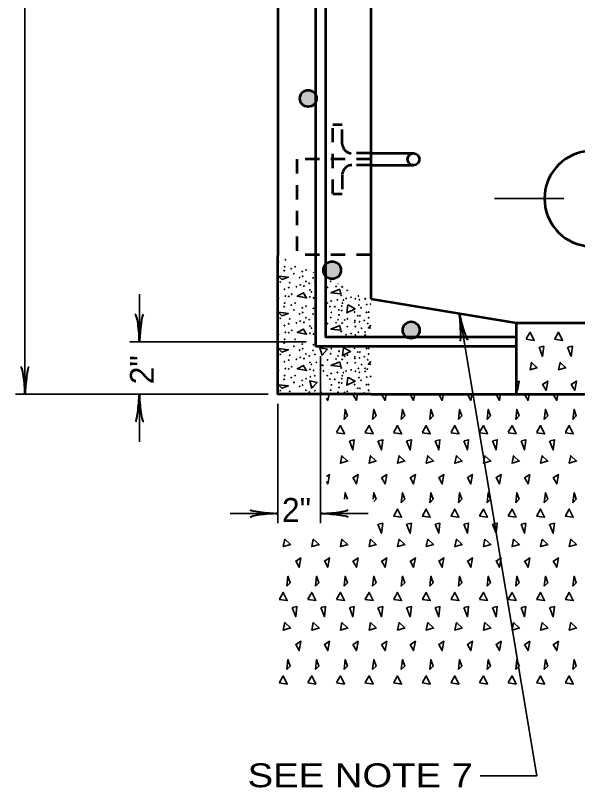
# Model space of a CAD drawing. Extents: x 788 to 1469, y -1 to 439.
# Drawn here: x 856.9 to 915.8, y 80.5 to 161.4 of the extents above; entities that cross this region are included whole.
import ezdxf

# ---------------------------------------------------------------- set-up
doc = ezdxf.new("R2010")
doc.units = 0
doc.linetypes.add('SHORT_DASHED', pattern=[2.7, 1.5, -1.2])
doc.layers.add('1', color=7, linetype='Continuous', lineweight=35)

msp = doc.modelspace()

# ---------------------------------------------------------------- hatches: boundary and pattern name
at = {"layer": '1'}
for points in [[(888.429, 152.704, 1), (886.678, 152.704, 1)], [(890.992, 134.704, 1), (889.144, 134.704, 1)], [(899.239, 128.43, 1), (897.469, 128.43, 1)]]:
    msp.add_hatch(color=256, dxfattribs=at).paths.add_polyline_path(points)

# ---------------------------------------------------------------- linework, layer by layer
for p, q in [((857.856, 195.872), (857.856, 121.703)), ((907.106, 142.203), (914.356, 142.203)), ((869.856, 127.203), (869.856, 132.203)), ((887.356, 127.203), (868.856, 127.203)), ((888.856, 125.703), (888.856, 108.203)), ((883.356, 121.703), (856.856, 121.703)), ((869.856, 121.703), (869.856, 116.703)), ((892.333, 121.738), (892.231, 121.673)), ((895.333, 121.738), (895.231, 121.673)), ((898.333, 121.738), (898.231, 121.673)), ((901.333, 121.738), (901.231, 121.673)), ((904.333, 121.738), (904.231, 121.673)), ((907.333, 121.738), (907.231, 121.673)), ((910.333, 121.738), (910.231, 121.673)), ((913.333, 121.738), (913.231, 121.673)), ((884.356, 120.703), (884.356, 108.203)), ((884.356, 109.203), (879.356, 109.203)), ((888.856, 109.203), (893.856, 109.203))]:
    msp.add_line(p, q, dxfattribs=at)
at = {"layer": '1', "lineweight": 53}
for p, q in [((884.356, 165.102), (884.356, 136.23)), ((894.126, 165.102), (894.126, 131.703)), ((894.126, 146.953), (898.626, 146.953)), ((894.126, 145.703), (898.626, 145.703)), ((894.126, 131.703), (909.356, 129.203)), ((909.356, 129.203), (925.356, 129.203)), ((909.356, 129.203), (909.356, 121.703)), ((894.126, 121.703), (939.409, 121.703))]:
    msp.add_line(p, q, dxfattribs=at)
at = {"layer": '1', "linetype": 'SHORT_DASHED', "lineweight": 53}
for p, q in [((891.126, 147.953), (891.126, 149.953)), ((894.126, 146.953), (892.126, 146.953)), ((894.126, 146.328), (886.366, 146.328)), ((886.366, 146.328), (886.366, 136.328)), ((894.126, 145.703), (892.126, 145.703)), ((891.126, 144.703), (891.126, 142.703)), ((890.126, 142.703), (891.126, 142.703)), ((894.126, 136.328), (886.366, 136.328))]:
    msp.add_line(p, q, dxfattribs=at)
at = {"layer": '1', "lineweight": 53}
msp.add_lwpolyline([(888.356, 126.703), (888.356, 187.287), (889.356, 187.287), (889.356, 127.703), (909.356, 127.703), (909.356, 126.703)], close=True, dxfattribs=at)
at = {"layer": '1', "linetype": 'SHORT_DASHED', "lineweight": 53}
msp.add_lwpolyline([(890.126, 142.703), (890.126, 149.953), (891.126, 149.953)], dxfattribs=at)
at = {"layer": '1', "lineweight": 53}
msp.add_lwpolyline([(894.126, 121.703), (884.356, 121.703), (884.356, 136.23)], dxfattribs=at)
at = {"layer": '1'}
for points in [[(884.356, 136.21), (884.363, 136.21), (884.356, 136.223)], [(890.883, 132.71), (889.943, 132.33), (890.983, 132.21), (890.883, 132.67)], [(884.356, 132.41), (884.363, 132.41), (884.356, 132.423)], [(887.063, 132.33), (886.403, 131.97), (887.383, 131.79), (887.023, 132.35)], [(891.763, 131.07), (892.463, 130.67), (891.603, 130.25), (891.723, 131.09)], [(903.41, 130.179), (911.52, 81.73), (905.579, 81.73)], [(890.883, 128.91), (889.943, 128.53), (890.983, 128.41), (890.883, 128.87)], [(894.126, 128.927), (893.863, 128.65), (894.126, 128.632)], [(884.356, 128.61), (884.363, 128.61), (884.356, 128.623)], [(887.063, 128.53), (886.403, 128.17), (887.383, 127.99), (887.023, 128.55)], [(910.417, 127.505), (910.817, 128.205), (911.237, 127.345), (910.397, 127.465)], [(913.417, 127.505), (913.817, 128.205), (914.237, 127.345), (913.397, 127.465)], [(889.023, 125.774), (888.783, 126.574), (889.563, 126.414), (889.003, 125.814)], [(891.3, 126.567), (892, 126.167), (891.14, 125.747), (891.26, 126.587)], [(911.757, 126.625), (912.137, 125.665), (912.257, 126.725), (911.797, 126.625)], [(914.757, 126.625), (915.137, 125.665), (915.257, 126.725), (914.797, 126.625)], [(884.356, 124.81), (884.363, 124.81), (884.356, 124.823)], [(887.063, 124.73), (886.403, 124.37), (887.383, 124.19), (887.023, 124.75)], [(890.883, 125.11), (889.943, 124.73), (890.983, 124.61), (890.883, 125.07)], [(894.126, 125.127), (893.863, 124.85), (894.126, 124.832)], [(911.617, 124.505), (910.817, 124.265), (910.977, 125.045), (911.577, 124.485)], [(914.617, 124.505), (913.817, 124.265), (913.977, 125.045), (914.577, 124.485)], [(887.95, 122.307), (887.711, 123.107), (888.49, 122.947), (887.93, 122.347)], [(891.763, 123.47), (892.463, 123.07), (891.603, 122.65), (891.723, 123.49)], [(909.356, 122.363), (909.497, 122.105), (909.677, 123.085), (909.356, 122.879)], [(912.137, 122.765), (912.497, 122.105), (912.677, 123.085), (912.117, 122.725)], [(915.137, 122.765), (915.497, 122.105), (915.677, 123.085), (915.117, 122.725)], [(889.485, 121.285), (889.611, 121.053), (889.737, 121.738)], [(892.251, 121.713), (892.611, 121.053), (892.737, 121.738)], [(895.251, 121.713), (895.611, 121.053), (895.737, 121.738)], [(898.251, 121.713), (898.611, 121.053), (898.737, 121.738)], [(901.251, 121.713), (901.611, 121.053), (901.737, 121.738)], [(904.251, 121.713), (904.611, 121.053), (904.737, 121.738)], [(907.251, 121.713), (907.611, 121.053), (907.737, 121.738)], [(910.251, 121.713), (910.611, 121.053), (910.737, 121.738)], [(913.251, 121.713), (913.611, 121.053), (913.737, 121.738)], [(890.531, 117.713), (890.931, 118.413), (891.351, 117.553), (890.511, 117.673)], [(893.531, 117.713), (893.931, 118.413), (894.351, 117.553), (893.511, 117.673)], [(896.531, 117.713), (896.931, 118.413), (897.351, 117.553), (896.511, 117.673)], [(899.531, 117.713), (899.931, 118.413), (900.351, 117.553), (899.511, 117.673)], [(902.531, 117.713), (902.931, 118.413), (903.351, 117.553), (902.511, 117.673)], [(905.531, 117.713), (905.931, 118.413), (906.351, 117.553), (905.511, 117.673)], [(908.531, 117.713), (908.931, 118.413), (909.351, 117.553), (908.511, 117.673)], [(911.531, 117.713), (911.931, 118.413), (912.351, 117.553), (911.511, 117.673)], [(914.531, 117.713), (914.931, 118.413), (915.351, 117.553), (914.511, 117.673)], [(891.871, 116.833), (892.251, 115.873), (892.371, 116.933), (891.911, 116.833)], [(894.871, 116.833), (895.251, 115.873), (895.371, 116.933), (894.911, 116.833)], [(897.871, 116.833), (898.251, 115.873), (898.371, 116.933), (897.911, 116.833)], [(900.871, 116.833), (901.251, 115.873), (901.371, 116.933), (900.911, 116.833)], [(903.871, 116.833), (904.251, 115.873), (904.371, 116.933), (903.911, 116.833)], [(906.871, 116.833), (907.251, 115.873), (907.371, 116.933), (906.911, 116.833)], [(909.871, 116.833), (910.251, 115.873), (910.371, 116.933), (909.911, 116.833)], [(912.871, 116.833), (913.251, 115.873), (913.371, 116.933), (912.911, 116.833)], [(891.731, 114.713), (890.931, 114.473), (891.091, 115.253), (891.692, 114.693)], [(894.731, 114.713), (893.931, 114.473), (894.091, 115.253), (894.692, 114.693)], [(897.731, 114.713), (896.931, 114.473), (897.091, 115.253), (897.692, 114.693)], [(900.731, 114.713), (899.931, 114.473), (900.091, 115.253), (900.692, 114.693)], [(903.731, 114.713), (902.931, 114.473), (903.091, 115.253), (903.692, 114.693)], [(906.731, 114.713), (905.931, 114.473), (906.091, 115.253), (906.692, 114.693)], [(909.731, 114.713), (908.931, 114.473), (909.091, 115.253), (909.692, 114.693)], [(912.731, 114.713), (911.931, 114.473), (912.091, 115.253), (912.692, 114.693)], [(915.731, 114.713), (914.931, 114.473), (915.091, 115.253), (915.692, 114.693)], [(889.485, 112.545), (889.611, 112.313), (889.791, 113.293), (889.485, 113.095)], [(892.251, 112.973), (892.611, 112.313), (892.791, 113.293), (892.231, 112.933)], [(895.251, 112.973), (895.611, 112.313), (895.791, 113.293), (895.231, 112.933)], [(898.251, 112.973), (898.611, 112.313), (898.791, 113.293), (898.231, 112.933)], [(901.251, 112.973), (901.611, 112.313), (901.791, 113.293), (901.231, 112.933)], [(904.251, 112.973), (904.611, 112.313), (904.791, 113.293), (904.231, 112.933)], [(907.251, 112.973), (907.611, 112.313), (907.791, 113.293), (907.231, 112.933)], [(910.251, 112.973), (910.611, 112.313), (910.791, 113.293), (910.231, 112.933)], [(913.251, 112.973), (913.611, 112.313), (913.791, 113.293), (913.231, 112.933)], [(891.355, 110.711), (891.431, 111.373), (891.665, 110.711)], [(894.355, 110.711), (894.431, 111.373), (894.671, 110.693), (894.435, 110.456)], [(896.531, 108.973), (896.931, 109.673), (897.351, 108.813), (896.511, 108.933)], [(899.531, 108.973), (899.931, 109.673), (900.351, 108.813), (899.511, 108.933)], [(902.531, 108.973), (902.931, 109.673), (903.351, 108.813), (902.511, 108.933)], [(905.531, 108.973), (905.931, 109.673), (906.351, 108.813), (905.511, 108.933)], [(908.531, 108.973), (908.931, 109.673), (909.351, 108.813), (908.511, 108.933)], [(911.531, 108.973), (911.931, 109.673), (912.351, 108.813), (911.511, 108.933)], [(914.531, 108.973), (914.931, 109.673), (915.351, 108.813), (914.511, 108.933)], [(894.871, 108.093), (895.251, 107.133), (895.371, 108.193), (894.911, 108.093)], [(897.871, 108.093), (898.251, 107.133), (898.371, 108.193), (897.911, 108.093)], [(900.871, 108.093), (901.251, 107.133), (901.371, 108.193), (900.911, 108.093)], [(903.871, 108.093), (904.251, 107.133), (904.371, 108.193), (903.911, 108.093)], [(906.871, 108.093), (907.251, 107.133), (907.371, 108.193), (906.911, 108.093)], [(909.871, 108.093), (910.251, 107.133), (910.371, 108.193), (909.911, 108.093)], [(912.871, 108.093), (913.251, 107.133), (913.371, 108.193), (912.911, 108.093)], [(885.731, 105.973), (884.931, 105.733), (885.091, 106.513), (885.692, 105.953)], [(888.731, 105.973), (887.931, 105.733), (888.091, 106.513), (888.692, 105.953)], [(891.731, 105.973), (890.931, 105.733), (891.091, 106.513), (891.692, 105.953)], [(894.731, 105.973), (893.931, 105.733), (894.091, 106.513), (894.692, 105.953)], [(897.731, 105.973), (896.931, 105.733), (897.091, 106.513), (897.692, 105.953)], [(900.731, 105.973), (899.931, 105.733), (900.091, 106.513), (900.692, 105.953)], [(903.731, 105.973), (902.931, 105.733), (903.091, 106.513), (903.692, 105.953)], [(906.731, 105.973), (905.931, 105.733), (906.091, 106.513), (906.692, 105.953)], [(909.731, 105.973), (908.931, 105.733), (909.091, 106.513), (909.692, 105.953)], [(912.731, 105.973), (911.931, 105.733), (912.091, 106.513), (912.692, 105.953)], [(915.731, 105.973), (914.931, 105.733), (915.091, 106.513), (915.692, 105.953)], [(886.251, 104.233), (886.611, 103.573), (886.791, 104.553), (886.231, 104.193)], [(889.251, 104.233), (889.611, 103.573), (889.791, 104.553), (889.231, 104.193)], [(892.251, 104.233), (892.611, 103.573), (892.791, 104.553), (892.231, 104.193)], [(895.251, 104.233), (895.611, 103.573), (895.791, 104.553), (895.231, 104.193)], [(898.251, 104.233), (898.611, 103.573), (898.791, 104.553), (898.231, 104.193)], [(901.251, 104.233), (901.611, 103.573), (901.791, 104.553), (901.231, 104.193)], [(904.251, 104.233), (904.611, 103.573), (904.791, 104.553), (904.231, 104.193)], [(907.251, 104.233), (907.611, 103.573), (907.791, 104.553), (907.231, 104.193)], [(910.251, 104.233), (910.611, 103.573), (910.791, 104.553), (910.231, 104.193)], [(913.251, 104.233), (913.611, 103.573), (913.791, 104.553), (913.231, 104.193)], [(884.531, 100.233), (884.931, 100.933), (885.351, 100.073), (884.511, 100.193)], [(887.531, 100.233), (887.931, 100.933), (888.351, 100.073), (887.511, 100.193)], [(890.531, 100.233), (890.931, 100.933), (891.351, 100.073), (890.511, 100.193)], [(893.531, 100.233), (893.931, 100.933), (894.351, 100.073), (893.511, 100.193)], [(896.531, 100.233), (896.931, 100.933), (897.351, 100.073), (896.511, 100.193)], [(899.531, 100.233), (899.931, 100.933), (900.351, 100.073), (899.511, 100.193)], [(902.531, 100.233), (902.931, 100.933), (903.351, 100.073), (902.511, 100.193)], [(905.531, 100.233), (905.931, 100.933), (906.351, 100.073), (905.511, 100.193)], [(908.531, 100.233), (908.931, 100.933), (909.351, 100.073), (908.511, 100.193)], [(911.531, 100.233), (911.931, 100.933), (912.351, 100.073), (911.511, 100.193)], [(914.531, 100.233), (914.931, 100.933), (915.351, 100.073), (914.511, 100.193)], [(885.871, 99.353), (886.251, 98.393), (886.371, 99.453), (885.911, 99.353)], [(888.871, 99.353), (889.251, 98.393), (889.371, 99.453), (888.911, 99.353)], [(891.871, 99.353), (892.251, 98.393), (892.371, 99.453), (891.911, 99.353)], [(894.871, 99.353), (895.251, 98.393), (895.371, 99.453), (894.911, 99.353)], [(897.871, 99.353), (898.251, 98.393), (898.371, 99.453), (897.911, 99.353)], [(900.871, 99.353), (901.251, 98.393), (901.371, 99.453), (900.911, 99.353)], [(903.871, 99.353), (904.251, 98.393), (904.371, 99.453), (903.911, 99.353)], [(906.871, 99.353), (907.251, 98.393), (907.371, 99.453), (906.911, 99.353)], [(909.871, 99.353), (910.251, 98.393), (910.371, 99.453), (909.911, 99.353)], [(912.871, 99.353), (913.251, 98.393), (913.371, 99.453), (912.911, 99.353)], [(885.731, 97.233), (884.931, 96.993), (885.091, 97.773), (885.692, 97.213)], [(888.731, 97.233), (887.931, 96.993), (888.091, 97.773), (888.692, 97.213)], [(891.731, 97.233), (890.931, 96.993), (891.091, 97.773), (891.692, 97.213)], [(894.731, 97.233), (893.931, 96.993), (894.091, 97.773), (894.692, 97.213)], [(897.731, 97.233), (896.931, 96.993), (897.091, 97.773), (897.692, 97.213)], [(900.731, 97.233), (899.931, 96.993), (900.091, 97.773), (900.692, 97.213)], [(903.731, 97.233), (902.931, 96.993), (903.091, 97.773), (903.692, 97.213)], [(906.731, 97.233), (905.931, 96.993), (906.091, 97.773), (906.692, 97.213)], [(909.731, 97.233), (908.931, 96.993), (909.091, 97.773), (909.692, 97.213)], [(912.731, 97.233), (911.931, 96.993), (912.091, 97.773), (912.692, 97.213)], [(915.731, 97.233), (914.931, 96.993), (915.091, 97.773), (915.692, 97.213)], [(886.251, 95.493), (886.611, 94.833), (886.791, 95.813), (886.231, 95.453)], [(889.251, 95.493), (889.611, 94.833), (889.791, 95.813), (889.231, 95.453)], [(892.251, 95.493), (892.611, 94.833), (892.791, 95.813), (892.231, 95.453)], [(895.251, 95.493), (895.611, 94.833), (895.791, 95.813), (895.231, 95.453)], [(898.251, 95.493), (898.611, 94.833), (898.791, 95.813), (898.231, 95.453)], [(901.251, 95.493), (901.611, 94.833), (901.791, 95.813), (901.231, 95.453)], [(904.251, 95.493), (904.611, 94.833), (904.791, 95.813), (904.231, 95.453)], [(907.251, 95.493), (907.611, 94.833), (907.791, 95.813), (907.231, 95.453)], [(910.251, 95.493), (910.611, 94.833), (910.791, 95.813), (910.231, 95.453)], [(913.251, 95.493), (913.611, 94.833), (913.791, 95.813), (913.231, 95.453)], [(884.531, 91.493), (884.931, 92.193), (885.351, 91.333), (884.511, 91.453)], [(887.531, 91.493), (887.931, 92.193), (888.351, 91.333), (887.511, 91.453)], [(890.531, 91.493), (890.931, 92.193), (891.351, 91.333), (890.511, 91.453)], [(893.531, 91.493), (893.931, 92.193), (894.351, 91.333), (893.511, 91.453)], [(896.531, 91.493), (896.931, 92.193), (897.351, 91.333), (896.511, 91.453)], [(899.531, 91.493), (899.931, 92.193), (900.351, 91.333), (899.511, 91.453)], [(902.531, 91.493), (902.931, 92.193), (903.351, 91.333), (902.511, 91.453)], [(905.531, 91.493), (905.931, 92.193), (906.351, 91.333), (905.511, 91.453)], [(908.531, 91.493), (908.931, 92.193), (909.351, 91.333), (908.511, 91.453)], [(911.531, 91.493), (911.931, 92.193), (912.351, 91.333), (911.511, 91.453)], [(914.531, 91.493), (914.931, 92.193), (915.351, 91.333), (914.511, 91.453)]]:
    msp.add_lwpolyline(points, dxfattribs=at)
for points in [[(884.443, 134.09), (885.483, 133.97), (884.803, 133.73)], [(884.443, 130.29), (885.483, 130.17), (884.803, 129.93)], [(884.443, 126.49), (885.483, 126.37), (884.803, 126.13)], [(884.443, 122.69), (885.483, 122.57), (884.803, 122.33)], [(891.312, 119.073), (891.431, 120.113), (891.671, 119.433)], [(894.312, 119.073), (894.431, 120.113), (894.671, 119.433)], [(897.312, 119.073), (897.431, 120.113), (897.671, 119.433)], [(900.312, 119.073), (900.431, 120.113), (900.671, 119.433)], [(903.312, 119.073), (903.431, 120.113), (903.671, 119.433)], [(906.312, 119.073), (906.431, 120.113), (906.671, 119.433)], [(909.312, 119.073), (909.431, 120.113), (909.671, 119.433)], [(912.312, 119.073), (912.431, 120.113), (912.671, 119.433)], [(915.312, 119.073), (915.431, 120.113), (915.671, 119.433)], [(897.312, 110.333), (897.431, 111.373), (897.671, 110.693)], [(900.312, 110.333), (900.431, 111.373), (900.671, 110.693)], [(903.312, 110.333), (903.431, 111.373), (903.671, 110.693)], [(906.312, 110.333), (906.431, 111.373), (906.671, 110.693)], [(909.312, 110.333), (909.431, 111.373), (909.671, 110.693)], [(912.312, 110.333), (912.431, 111.373), (912.671, 110.693)], [(915.312, 110.333), (915.431, 111.373), (915.671, 110.693)], [(885.312, 101.593), (885.431, 102.633), (885.671, 101.953)], [(888.312, 101.593), (888.431, 102.633), (888.671, 101.953)], [(891.312, 101.593), (891.431, 102.633), (891.671, 101.953)], [(894.312, 101.593), (894.431, 102.633), (894.671, 101.953)], [(897.312, 101.593), (897.431, 102.633), (897.671, 101.953)], [(900.312, 101.593), (900.431, 102.633), (900.671, 101.953)], [(903.312, 101.593), (903.431, 102.633), (903.671, 101.953)], [(906.312, 101.593), (906.431, 102.633), (906.671, 101.953)], [(909.312, 101.593), (909.431, 102.633), (909.671, 101.953)], [(912.312, 101.593), (912.431, 102.633), (912.671, 101.953)], [(915.312, 101.593), (915.431, 102.633), (915.671, 101.953)], [(885.312, 92.853), (885.431, 93.893), (885.671, 93.213)], [(888.312, 92.853), (888.431, 93.893), (888.671, 93.213)], [(891.312, 92.853), (891.431, 93.893), (891.671, 93.213)], [(894.312, 92.853), (894.431, 93.893), (894.671, 93.213)], [(897.312, 92.853), (897.431, 93.893), (897.671, 93.213)], [(900.312, 92.853), (900.431, 93.893), (900.671, 93.213)], [(903.312, 92.853), (903.431, 93.893), (903.671, 93.213)], [(906.312, 92.853), (906.431, 93.893), (906.671, 93.213)], [(909.312, 92.853), (909.431, 93.893), (909.671, 93.213)], [(912.312, 92.853), (912.431, 93.893), (912.671, 93.213)], [(915.312, 92.853), (915.431, 93.893), (915.671, 93.213)]]:
    msp.add_lwpolyline(points, close=True, dxfattribs=at)
at = {"layer": '1', "lineweight": 53}
for centre, radius in [((887.554, 152.704), 0.875), ((898.597, 146.326), 0.625), ((890.068, 134.704), 0.924), ((898.354, 128.43), 0.885)]:
    msp.add_circle(centre, radius, dxfattribs=at)
at = {"layer": '1'}
for centre in [(884.451, 135.567), (885.166, 135.792), (885.034, 134.665), (885.087, 135.063), (885.776, 134.851), (886.054, 134.334), (886.174, 135.063), (886.929, 134.559), (887.34, 134.732), (886.651, 133.923), (886.969, 134.069), (887.313, 133.525), (888.069, 133.897), (889.924, 133.539), (884.623, 133.472), (885.06, 132.708), (885.511, 132.881), (885.617, 133.393), (886.319, 132.973), (886.717, 133.167), (887.115, 133.04), (887.671, 133.326), (888.254, 133.472), (889.593, 132.907), (890.481, 133), (891.117, 132.96), (885.166, 131.992), (885.511, 131.953), (885.829, 132.191), (887.737, 132.642), (887.737, 131.9), (887.896, 132.43), (891.011, 132.072), (891.647, 132.589), (892.058, 131.86), (892.827, 132.006), (884.451, 131.767), (885.087, 131.263), (885.776, 131.051), (886.174, 131.263), (888.122, 131.807), (889.553, 131.263), (889.964, 131.489), (890.613, 131.581), (891.144, 131.25), (891.25, 131.568), (891.528, 131.74), (892.509, 131.714), (892.88, 131.051), (892.933, 131.608), (893.529, 131.701), (893.688, 131.104), (885.034, 130.865), (886.054, 130.534), (886.929, 130.759), (886.969, 130.269), (887.34, 130.932), (888.109, 130.693), (889.831, 130.892), (889.99, 130.282), (890.348, 130.865), (890.772, 130.534), (891.064, 130.468), (891.077, 130.945), (892.416, 130.322), (893.105, 130.759), (893.668, 130.293), (893.895, 130.309), (884.623, 129.672), (885.617, 129.593), (886.651, 130.123), (887.313, 129.725), (887.671, 129.526), (888.069, 130.097), (889.924, 129.739), (890.693, 129.513), (890.786, 130.017), (891.395, 129.487), (891.674, 129.606), (892.747, 129.924), (892.972, 129.924), (893.436, 129.434), (893.895, 129.712), (885.06, 128.908), (885.511, 129.081), (886.319, 129.173), (886.717, 129.367), (887.115, 129.24), (887.737, 128.842), (887.896, 128.63), (889.593, 129.107), (890.481, 129.2), (891.117, 129.16), (891.647, 128.789), (892.442, 129.253), (892.456, 129.42), (892.482, 128.802), (892.946, 129.306), (893.802, 129.12), (884.451, 127.967), (885.166, 128.192), (885.511, 128.153), (885.829, 128.391), (887.737, 128.1), (888.122, 128.007), (891.011, 128.272), (891.528, 127.94), (892.058, 128.06), (892.509, 127.914), (892.827, 128.206), (893.158, 128.617), (893.516, 128.219), (893.529, 127.901), (885.034, 127.065), (885.087, 127.463), (886.174, 127.463), (886.054, 126.734), (886.651, 126.323), (886.929, 126.959), (886.969, 126.469), (888.069, 126.297), (888.109, 126.893), (889.99, 126.482), (890.786, 126.217), (892.416, 126.522), (893.668, 126.493), (893.895, 126.509), (884.623, 125.872), (885.617, 125.793), (886.717, 125.567), (887.115, 125.44), (887.313, 125.925), (887.671, 125.726), (888.254, 125.872), (889.924, 125.939), (890.481, 125.4), (890.693, 125.713), (891.395, 125.687), (891.674, 125.806), (892.442, 125.453), (892.456, 125.62), (892.747, 126.124), (892.946, 125.506), (892.972, 126.124), (893.436, 125.634), (893.895, 125.912), (885.06, 125.108), (885.511, 125.281), (885.829, 124.591), (886.319, 125.373), (887.737, 125.042), (887.896, 124.83), (888.413, 125.042), (889.036, 124.737), (889.089, 124.737), (889.593, 125.307), (891.117, 125.36), (891.647, 124.989), (892.482, 125.002), (893.158, 124.817), (893.802, 125.32), (884.451, 124.167), (885.166, 124.392), (885.511, 124.353), (887.737, 124.3), (888.122, 124.207), (889.156, 124.154), (889.964, 123.889), (890.613, 123.981), (891.011, 124.472), (891.25, 123.968), (891.528, 124.14), (892.058, 124.26), (892.509, 124.114), (892.827, 124.406), (892.933, 124.008), (893.516, 124.419), (893.529, 124.101), (893.749, 124.339), (885.034, 123.265), (885.087, 123.663), (885.776, 123.451), (886.174, 123.663), (886.929, 123.159), (887.34, 123.332), (887.794, 123.537), (888.241, 123.637), (889.553, 123.663), (889.831, 123.292), (890.348, 123.265), (891.077, 123.345), (891.144, 123.65), (892.88, 123.451), (893.105, 123.159), (893.688, 123.504), (886.054, 122.934), (886.651, 122.523), (886.969, 122.669), (888.069, 122.497), (889.99, 122.682), (890.772, 122.934), (890.786, 122.417), (891.064, 122.868), (892.416, 122.722), (892.747, 122.324), (892.972, 122.324), (893.668, 122.693), (893.895, 122.709), (884.623, 122.072), (885.617, 121.993), (886.717, 121.767), (887.313, 122.125), (887.671, 121.926), (888.254, 122.072), (888.904, 121.926), (889.924, 122.139), (890.693, 121.913), (891.395, 121.887), (891.674, 122.006), (892.456, 121.82), (893.436, 121.834), (893.895, 122.112)]:
    msp.add_circle(centre, 0.0265, dxfattribs=at)
at = {"layer": '1', "linetype": 'SHORT_DASHED', "lineweight": 53}
for centre, start, end in [((892.126, 147.953), 180, 270), ((892.126, 144.703), 90, 180)]:
    msp.add_arc(centre, 1, start, end, dxfattribs=at)
at = {"layer": '1', "lineweight": 53}
msp.add_arc((917.335, 142.203), 5, 17.38217, 342.61783, dxfattribs=at)
at = {"layer": '1'}
for centre, start, end in [((884.358, 134.44), 266.41343, 93.58658), ((888.109, 134.493), 158.73033, 331.54608), ((890.693, 133.313), 197.15661, 293.1198), ((894.107, 131.157), 41.80177, 318.19823), ((884.358, 130.64), 266.41343, 93.58658), ((884.358, 126.84), 266.41343, 93.58658), ((884.358, 123.04), 266.41343, 93.58658), ((894.107, 123.557), 41.80177, 318.19823), ((892.946, 121.706), 353.24736, 186.75264)]:
    msp.add_arc(centre, 0.0265, start, end, dxfattribs=at)
at = {"layer": '1', "lineweight": 40}
for centre, major_axis, ratio, start_param, end_param in [((869.58, 128.294), (0.156, -1.786), 0.122415, 0.896353, 3.141593), ((869.58, 128.294), (0.156, -1.786), 0.122415, 0.896353, 3.141593), ((870.068, 128.323), (-0.176, -1.756), 0.07063, 3.140715, 5.41811), ((870.068, 128.323), (-0.176, -1.756), 0.07063, 3.140715, 5.41811), ((903.387, 129.039), (0.117, -1.761), 0.07063, 6.282307, 8.559703), ((903.863, 129.148), (-0.449, 1.735), 0.122415, 0.896353, 3.141593), ((857.58, 122.794), (0.156, -1.786), 0.122415, 0.896353, 3.141593), ((858.068, 122.823), (-0.176, -1.756), 0.07063, 3.140715, 5.41811), ((869.645, 120.582), (0.176, 1.756), 0.07063, 3.140715, 5.41811), ((869.645, 120.582), (0.176, 1.756), 0.07063, 3.140715, 5.41811), ((870.133, 120.612), (-0.156, 1.786), 0.122415, 0.896353, 3.141593), ((870.133, 120.612), (-0.156, 1.786), 0.122415, 0.896353, 3.141593), ((883.236, 109.414), (1.756, -0.176), 0.07063, 3.140715, 5.41811), ((883.236, 109.414), (1.756, -0.176), 0.07063, 3.140715, 5.41811), ((889.947, 109.479), (-1.786, -0.156), 0.122415, 0.896353, 3.141593), ((889.947, 109.479), (-1.786, -0.156), 0.122415, 0.896353, 3.141593), ((883.265, 108.927), (1.786, 0.156), 0.122415, 0.896353, 3.141593), ((883.265, 108.927), (1.786, 0.156), 0.122415, 0.896353, 3.141593), ((889.977, 108.991), (-1.756, 0.176), 0.07063, 3.140715, 5.41811), ((889.977, 108.991), (-1.756, 0.176), 0.07063, 3.140715, 5.41811)]:
    msp.add_ellipse(centre, major_axis=major_axis, ratio=ratio, start_param=start_param, end_param=end_param, dxfattribs=at)

# ---------------------------------------------------------------- texts
at = {"layer": '1'}
msp.add_text('2"', height=2.5, rotation=90, dxfattribs=at).set_placement((871.367, 122.741))
msp.add_text('2"', height=2.5, dxfattribs=at).set_placement((884.803, 108.331))
at = {"layer": '1', "width": 1.2}
msp.add_text('SEE NOTE 7', height=2.5, dxfattribs=at).set_placement((881.201, 80.523))

doc.saveas('drawing.dxf')
